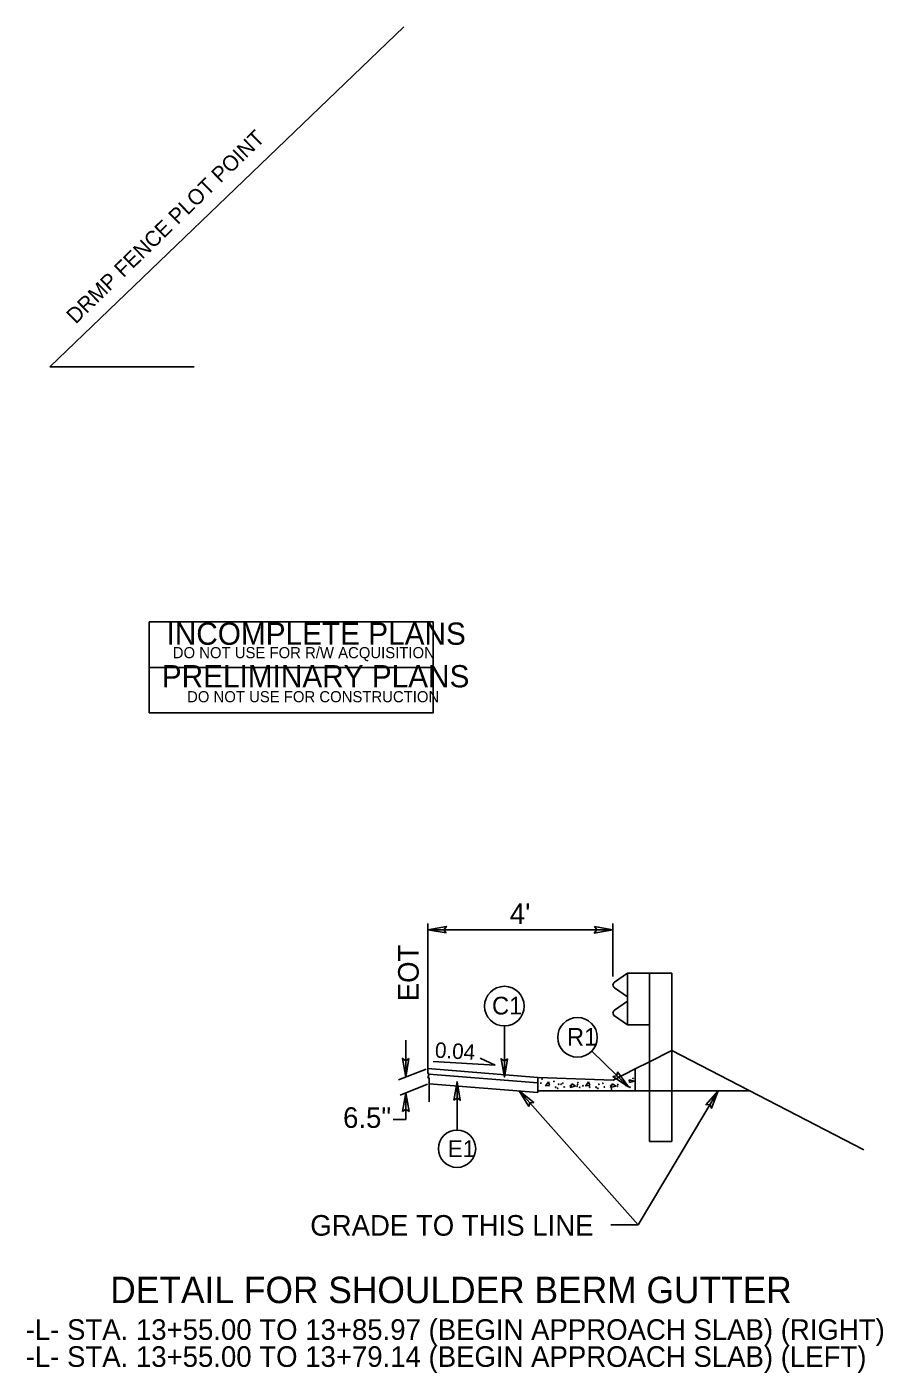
# Model space of a CAD drawing. Extents: x 1542177 to 1542464, y 45134 to 45344.
# Drawn here: x 1542363 to 1542396.3, y 45292.2 to 45344.4 of the extents above; entities that cross this region are included whole.
import ezdxf

# ---------------------------------------------------------------- set-up
doc = ezdxf.new("R2010")
doc.units = 0
for name, color, linetype in [('Default', 7, 'Continuous'), ('Old_Level_1', 7, 'Continuous'), ('Old_Level_2', 7, 'Continuous'), ('Typical Curb CELL', 7, 'Continuous'), ('Typical Guardrail CELL', 7, 'Continuous'), ('Typical ID Circle CELL', 7, 'Continuous'), ('Typical Terminator CELL', 7, 'Continuous'), ('Typical Text ID Circle CELL', 7, 'Continuous')]:
    doc.layers.add(name, color=color, linetype=linetype)

msp = doc.modelspace()

# ---------------------------------------------------------------- linework, layer by layer
at = {"layer": 'Default'}
for p, q in [((1542363.923, 45331.251), (1542377.663, 45344.446)), ((1542363.923, 45331.251), (1542369.524, 45331.251)), ((1542378.594, 45303.815), (1542378.594, 45309.642)), ((1542385.787, 45309.396), (1542378.594, 45309.396)), ((1542385.787, 45307.574), (1542385.787, 45309.642)), ((1542377.741, 45303.673), (1542377.741, 45305.108)), ((1542388.074, 45304.702), (1542395.521, 45300.844)), ((1542378.809, 45304.286), (1542381.213, 45304.141)), ((1542381.213, 45304.141), (1542380.631, 45304.409)), ((1542378.535, 45303.982), (1542377.467, 45303.567)), ((1542378.594, 45304.005), (1542382.875, 45303.665)), ((1542378.594, 45303.815), (1542378.652, 45303.815)), ((1542378.594, 45303.645), (1542378.652, 45303.815)), ((1542378.594, 45303.645), (1542378.652, 45303.645)), ((1542378.645, 45303.793), (1542382.875, 45303.457)), ((1542378.652, 45302.715), (1542378.652, 45303.645)), ((1542378.593, 45303.394), (1542377.525, 45302.979)), ((1542377.741, 45302.033), (1542377.741, 45303.063)), ((1542378.652, 45303.418), (1542382.875, 45303.082)), ((1542382.875, 45303.082), (1542382.875, 45303.144)), ((1542386.651, 45303.144), (1542391.081, 45303.144)), ((1542377.741, 45302.033), (1542377.251, 45302.033))]:
    msp.add_line(p, q, dxfattribs=at)
for points in [[(1542367.783, 45319.581), (1542367.783, 45321.343), (1542378.808, 45321.343), (1542378.808, 45319.581)], [(1542367.783, 45317.818), (1542367.783, 45319.581), (1542378.808, 45319.581), (1542378.808, 45317.818)], [(1542379.314, 45309.272), (1542378.594, 45309.396), (1542379.318, 45309.524), (1542379.226, 45309.396)], [(1542385.067, 45309.52), (1542385.787, 45309.396), (1542385.063, 45309.268), (1542385.155, 45309.396)], [(1542377.865, 45304.393), (1542377.741, 45303.673), (1542377.613, 45304.397), (1542377.741, 45304.305)], [(1542377.617, 45302.343), (1542377.741, 45303.063), (1542377.869, 45302.339), (1542377.741, 45302.431)]]:
    msp.add_lwpolyline(points, close=True, dxfattribs=at)
at = {"layer": 'Old_Level_2'}
for points in [[(1542382.141, 45303.14), (1542386.763, 45297.943), (1542385.701, 45297.942)], [(1542389.867, 45303.144), (1542386.763, 45297.943), (1542385.701, 45297.942)]]:
    msp.add_lwpolyline(points, dxfattribs=at)
at = {"layer": 'Typical Curb CELL'}
for p, q in [((1542387.211, 45304.271), (1542388.074, 45304.702)), ((1542386.651, 45303.991), (1542387.211, 45304.271)), ((1542382.875, 45303.665), (1542382.875, 45303.665)), ((1542382.875, 45303.144), (1542382.875, 45303.652)), ((1542382.889, 45303.665), (1542385.791, 45303.561)), ((1542385.791, 45303.561), (1542386.651, 45303.991)), ((1542386.412, 45303.574), (1542386.433, 45303.461)), ((1542386.605, 45303.518), (1542386.412, 45303.574)), ((1542386.651, 45303.144), (1542386.651, 45303.991)), ((1542386.651, 45303.144), (1542382.875, 45303.144)), ((1542383.172, 45303.334), (1542383.28, 45303.484)), ((1542383.323, 45303.342), (1542383.172, 45303.334)), ((1542383.28, 45303.484), (1542383.323, 45303.342)), ((1542384.129, 45303.27), (1542384.207, 45303.414)), ((1542384.336, 45303.32), (1542384.129, 45303.27)), ((1542384.207, 45303.414), (1542384.336, 45303.32)), ((1542384.734, 45303.334), (1542384.841, 45303.484)), ((1542384.884, 45303.342), (1542384.734, 45303.334)), ((1542384.841, 45303.484), (1542384.884, 45303.342)), ((1542385.69, 45303.27), (1542385.768, 45303.414)), ((1542385.897, 45303.32), (1542385.69, 45303.27)), ((1542385.768, 45303.414), (1542385.897, 45303.32)), ((1542386.433, 45303.461), (1542386.605, 45303.518))]:
    msp.add_line(p, q, dxfattribs=at)
for centre in [(1542383.035, 45303.599), (1542386.57, 45303.625), (1542382.988, 45303.443), (1542383.494, 45303.506), (1542383.568, 45303.283), (1542383.638, 45303.241), (1542383.679, 45303.399), (1542383.774, 45303.396), (1542383.836, 45303.435), (1542383.895, 45303.29), (1542384.138, 45303.339), (1542384.395, 45303.319), (1542384.416, 45303.382), (1542384.429, 45303.456), (1542384.5, 45303.277), (1542384.62, 45303.335), (1542384.737, 45303.346), (1542384.887, 45303.283), (1542385.13, 45303.283), (1542385.2, 45303.241), (1542385.241, 45303.399), (1542385.398, 45303.435), (1542385.456, 45303.29), (1542385.699, 45303.339), (1542385.735, 45303.212), (1542385.956, 45303.319), (1542385.977, 45303.382), (1542386.298, 45303.346), (1542386.448, 45303.283)]:
    msp.add_circle(centre, 0.01, dxfattribs=at)
msp.add_arc((1542382.888, 45303.652), 0.013, 87.952, 180, dxfattribs=at)
at = {"layer": 'Typical Guardrail CELL'}
for p, q in [((1542386.348, 45307.712), (1542385.845, 45307.36)), ((1542387.211, 45307.712), (1542386.348, 45307.712)), ((1542386.348, 45307.712), (1542386.348, 45305.699)), ((1542387.211, 45307.712), (1542387.211, 45304.271)), ((1542387.211, 45307.712), (1542388.074, 45307.712)), ((1542388.074, 45307.712), (1542388.074, 45304.702)), ((1542386.348, 45306.786), (1542385.845, 45307.138)), ((1542386.348, 45306.705), (1542386.348, 45306.786)), ((1542386.348, 45306.705), (1542386.348, 45306.624)), ((1542386.348, 45306.624), (1542385.845, 45306.272)), ((1542386.348, 45305.699), (1542385.845, 45306.051)), ((1542387.211, 45305.699), (1542386.348, 45305.699)), ((1542388.074, 45304.702), (1542388.074, 45301.172)), ((1542387.211, 45304.271), (1542387.211, 45301.172)), ((1542387.211, 45301.172), (1542388.074, 45301.172))]:
    msp.add_line(p, q, dxfattribs=at)
for centre, start, end in [((1542385.922, 45307.249), 125.003, 235.0112), ((1542385.922, 45306.161), 125.0059, 235.0366)]:
    msp.add_arc(centre, 0.135, start, end, dxfattribs=at)
at = {"layer": 'Typical ID Circle CELL'}
for p, q in [((1542381.571, 45305.661), (1542381.571, 45303.672)), ((1542384.961, 45304.68), (1542386.384, 45303.292)), ((1542379.733, 45301.618), (1542379.733, 45303.492))]:
    msp.add_line(p, q, dxfattribs=at)
for centre, radius in [((1542381.571, 45306.43), 0.769), ((1542384.41, 45305.217), 0.769), ((1542379.733, 45300.894), 0.725)]:
    msp.add_circle(centre, radius, dxfattribs=at)
at = {"layer": 'Typical Terminator CELL'}
for points in [[(1542381.693, 45304.385), (1542381.571, 45303.672), (1542381.444, 45304.389), (1542381.571, 45304.297)], [(1542385.96, 45303.877), (1542386.384, 45303.292), (1542385.783, 45303.701), (1542385.936, 45303.728)], [(1542379.611, 45302.78), (1542379.733, 45303.492), (1542379.86, 45302.776), (1542379.733, 45302.867)], [(1542382.523, 45302.527), (1542382.141, 45303.14), (1542382.711, 45302.689), (1542382.556, 45302.673)], [(1542389.396, 45302.595), (1542389.867, 45303.144), (1542389.608, 45302.464), (1542389.546, 45302.607)]]:
    msp.add_lwpolyline(points, close=True, dxfattribs=at)

# ---------------------------------------------------------------- texts
at = {"layer": 'Default'}
for s, height, rotation, p in [('DRMP FENCE PLOT POINT', 0.6, 44.2152, (1542364.926, 45332.885)), ('EOT', 0.8, 90, (1542378.245, 45306.618)), ('0.04', 0.6, 356.5617, (1542378.862, 45304.432))]:
    msp.add_text(s, height=height, rotation=rotation, dxfattribs=at).set_placement(p)
for s, height, p in [('INCOMPLETE PLANS', 0.864, (1542368.455, 45320.458)), ('DO NOT USE FOR R/W ACQUISITION', 0.432, (1542368.698, 45319.937)), ('PRELIMINARY PLANS', 0.864, (1542368.271, 45318.805)), ('DO NOT USE FOR CONSTRUCTION', 0.432, (1542369.253, 45318.227)), ("4'", 0.8, (1542381.784, 45309.62)), ('6.5"', 0.8, (1542375.308, 45301.703)), ('DETAIL FOR SHOULDER BERM GUTTER', 1.02627, (1542366.271, 45294.899)), ('-L- STA. 13+55.00 TO 13+85.97 (BEGIN APPROACH SLAB) (RIGHT)', 0.8, (1542362.987, 45293.473)), ('-L- STA. 13+55.00 TO 13+79.14 (BEGIN APPROACH SLAB) (LEFT)', 0.8, (1542362.987, 45292.424))]:
    msp.add_text(s, height=height, dxfattribs=at).set_placement(p)
at = {"layer": 'Old_Level_1'}
msp.add_text('GRADE TO THIS LINE ', height=0.8, dxfattribs=at).set_placement((1542374.036, 45297.517))
at = {"layer": 'Typical Text ID Circle CELL'}
for s, height, rotation, p in [('C1', 0.6886, 360, (1542381.09, 45306.105)), ('R1', 0.6886, 0.0001, (1542384.001, 45304.892)), ('E1', 0.649, 360, (1542379.378, 45300.571))]:
    msp.add_text(s, height=height, rotation=rotation, dxfattribs=at).set_placement(p)

doc.saveas('drawing.dxf')
